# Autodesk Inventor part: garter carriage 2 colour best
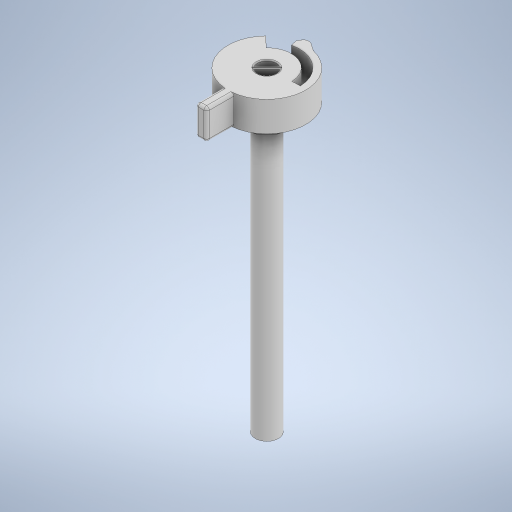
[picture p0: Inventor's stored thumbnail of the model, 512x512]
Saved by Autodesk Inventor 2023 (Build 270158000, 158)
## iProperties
Created: 2025-08
Part Number: garter carriage 2 colour best
Material: Generic
Document SubType Name: Modeling
Designer: susan
Density: 1 g/cm^3
Appearance: Default
Author: susan
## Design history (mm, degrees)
sketch "Sketch1"
  geometry: L1 (0, 0)-(215.925, -0.196); L2 (215.925, -0.196)-(215.648, -305.544); L3 (215.648, -305.544)-(-0.276, -305.348); L4 (-0.276, -305.348)-(0, 0); L5 (29.665, -20.2)-(29.665, -25.2); L6 (31.665, -20.2)-(31.665, -25.2); L7 (31.665, -20.58)-(31.665, -25.2); L8 (31.665, -25.2)-(31.665, -20.497); L9 (31.665, -20.2)-(29.665, -20.2); L10 (29.665, -20.497)-(29.665, -25.2); L11 (33.91, -35.397)-(35.821, -37.233); L12 (31.985, -38.133)-(32.238, -39.254); L13 (26.167, -32.404)-(24.667, -32.446); L14 (32.238, -39.254)-(31.899, -39.861); L15 (30.459, -40.196)-(29.092, -39.254); L16 (33.814, -25.86)-(34.036, -26.063); L17 (30.119, -30.356)-(28.699, -31.912); L18 (36.769, -28.556)-(36.547, -28.354); L19 (32.631, -32.647)-(31.211, -34.204); L20 (30.119, -30.356)-(28.699, -31.912); L21 (31.211, -34.204)-(32.631, -32.647); L22 (30.119, -30.356)-(28.699, -31.912); L23 (32.631, -32.647)-(31.211, -34.204); A1 r 7.15 centre (30.665, -32.28) between (35.821, -37.233) and (29.092, -39.254); A2 r 6 centre (30.665, -32.28) between (24.667, -32.446) and (31.985, -38.133); A3 r 4.5 centre (30.665, -32.28) between (26.167, -32.404) and (33.91, -35.397); A4 r 1 centre (31.026, -39.372) between (30.459, -40.196) and (31.899, -39.861); A5 r 2 centre (30.665, -32.28) between (28.699, -31.912) and (31.211, -34.204); A6 r 2 centre (30.665, -32.28) between (32.631, -32.647) and (30.119, -30.356); 3 further points
  constraints: 38 end point, 15 point on circle, 6 centre point, 5 coincident, 3 perpendicular, 2 tangent, 1 collinear, 2 other
  dimensions: "d75" = 0.3 distance of L16.start L16.end; "d76" = 0.3 distance of L18.start L18.end
extrude "Extrusion2" new body sketch "Sketch1" distance "d80" = 8.5; taper "d81" = 0 deg
sketch "Sketch3"
  geometry: L1 (-33.91, -35.397)-(-35.821, -37.233) reference; L2 (-32.792, -34.323)-(-33.737, -33.34); L3 (-33.737, -33.34)-(-31.848, -35.307); L4 (-28.538, -30.236)-(-29.483, -29.252); L5 (-29.483, -29.252)-(-27.593, -31.219); C1 r 13.427 at (-30.665, -32.28); A1 r 2 centre (-30.665, -32.28) between (-30.119, -30.356) and (-32.631, -32.647) reference; A2 r 2 centre (-30.665, -32.28) between (-31.211, -34.204) and (-28.699, -31.912) reference; A3 r 3.25 centre (-30.665, -32.28) between (-31.848, -35.307) and (-27.593, -31.219); A4 r 3.25 centre (-30.665, -32.28) between (-29.483, -29.252) and (-33.737, -33.34); 3 further points
  constraints: 8 end point, 4 point on circle, 3 centre point, 1 coincident
extrude "Extrusion3" cut sketch "Sketch3" distance "d88" = 3; taper "d89" = 0 deg
sketch "Sketch4"
  geometry: C1 r 2.25 at (-30.665, -32.28); C2 r 1.75 at (-30.665, -32.28); A1 r 2 centre (-30.665, -32.28) between (-30.119, -30.356) and (-32.631, -32.647) reference; 1 further point
  constraints: 2 centre point, 1 coincident
extrude "Extrusion4" join sketch "Sketch4" distance "d92" = 49; taper "d94" = 0 deg; dims "d93" = 8.5, "d95" = 0
node "Direct Edit1"
sketch "Sketch5"
  geometry: L1 (2.236, -0.25)-(-2.236, -0.25); L2 (-2.236, -0.25)-(2.236, -0.25); L3 (2.236, 0.25)-(-2.236, 0.25); L4 (-2.236, 0.25)-(2.236, 0.25); A1 r 2.25 centre (0, 0) between (-2.194, 0.5) and (-2.194, -0.5) reference; A2 r 2.25 centre (0, 0) between (-2.236, -0.25) and (-2.236, 0.25); A3 r 2.25 centre (0, 0) between (2.236, 0.25) and (2.236, -0.25); 7 further points
  constraints: 12 point on circle, 8 end point, 2 centre point, 1 coincident, 1 horizontal
extrude "Extrusion6" join sketch "Sketch5" stored distance "d130" = 10; taper "d131" = 0 deg
node "Direct Edit2"
thicken "Thicken6" dims "d135" = 0.1, "d136" = 0.1
node "Direct Edit3"
fillet "Fillet2" dims "d150" = 0.5
fillet "Fillet3" dims "d151" = 0.5
fillet "Fillet4" dims "d152" = 0.2
fillet "Fillet5" dims "d153" = 0.2
body "Solid2"
node "Image1"
move_body "Move1" dims "d98" = -9
move_body "Move2" dims "d134" = 0.5
feature "Rotate1" dims "d141" = 45 deg
other parameters: "d96" = 0, "d97" = 0, "d132" = 0, "d133" = 0
